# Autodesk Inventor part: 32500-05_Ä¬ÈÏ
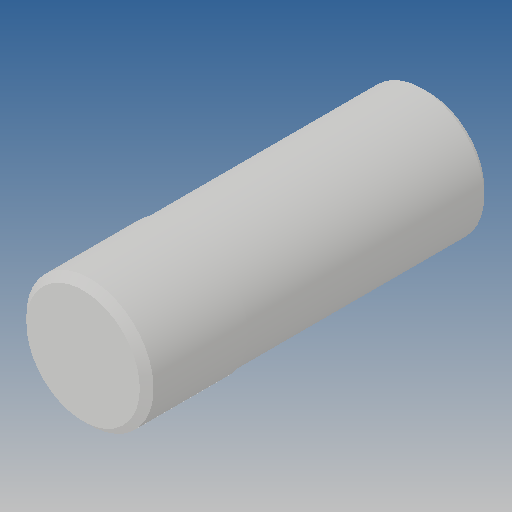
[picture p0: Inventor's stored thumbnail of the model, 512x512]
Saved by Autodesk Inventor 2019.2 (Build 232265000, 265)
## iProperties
Created: 2010-06
Part Number: 32500-05_Ä¬ÈÏ
Material: Ogólny
Document SubType Name: Modeling
Designer: CADENGINEERING4
Density: 1 g/cm^3
Appearance: Domyślna
Author: CADENGINEERING4
Revision Number: ÈÎºÎ
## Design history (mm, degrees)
feature "NONE"
node "Bryła1"
